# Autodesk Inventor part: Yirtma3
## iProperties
Created: 2008-12
Part Number: Yirtma3
Material: Default
Document SubType Name: Sheet Metal
Designer: Designer
Density: 1 g/cm^3
Sheet Metal Rule: Default_mm
Author: Designer
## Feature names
1. Bend2
